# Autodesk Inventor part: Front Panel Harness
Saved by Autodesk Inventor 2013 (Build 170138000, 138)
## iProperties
Created: 2007-02
Part Number: Front Panel Harness
Document SubType Name: Modeling
Designer: floress
Density: 1 g/cm^3
Material: Allgemein
GlobalPropertyList: <PropertyList/>
Key:2|1|1|0|4|0|0|0|19|0|0|0|Level:1: <CableProperty entityType="Connector" version="1.0"><ID editable="" value=""/><UserDefined><Property name="14121" value="0.125 in" unitCategory="14110" custom="
Key:2|1|1|0|8|0|0|0|1|0|0|0|29|0|0|0|Level:2: <CableProperty entityType="Connector" version="1.0"><ID editable="" value=""/><UserDefined><Property name="14121" value="0.125 in" unitCategory="14110" custom="
Author: floress
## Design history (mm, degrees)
workpoint "Work Point1"
workpoint "Work Point2"
sketch "Segment1"
workpoint "Work Point3"
workpoint "Work Point4"
workpoint "Work Point5"
workpoint "Work Point6"
workpoint "Work Point7"
workpoint "Work Point8"
workplane "Work Plane1"
sketch "Sketch1"
  geometry: C1 r 0.986 at (0, 0); 1 further point
  constraints: 1 centre point
feature "SweepSrf1" sketch "Sketch1" dims "d0" = 0
workpoint "Work Point9"
sketch "Segment2"
workpoint "Work Point10"
workplane "Work Plane2"
sketch "Sketch2"
  geometry: C1 r 0.61 at (0, 0); 1 further point
  constraints: 1 centre point
feature "SweepSrf2" sketch "Sketch2" dims "d1" = 0
workpoint "Work Point11"
sketch "Segment3"
workpoint "Work Point12"
workplane "Work Plane3"
sketch "Sketch3"
  geometry: C1 r 0.61 at (0, 0); 1 further point
  constraints: 1 centre point
feature "SweepSrf3" sketch "Sketch3" dims "d2" = 0
workpoint "Work Point13"
sketch "Segment4"
workpoint "Work Point14"
workplane "Work Plane4"
sketch "Sketch4"
  geometry: C1 r 0.61 at (0, 0); 1 further point
  constraints: 1 centre point
feature "SweepSrf4" sketch "Sketch4" dims "d3" = 0
workpoint "Work Point15"
workpoint "Work Point16"
sketch "Wire1"
workpoint "Work Point17"
workpoint "Work Point18"
sketch "Wire2"
workpoint "Work Point19"
workpoint "Work Point20"
sketch "Wire3"
workpoint "Work Point21"
workpoint "Work Point22"
sketch "Wire4"
workpoint "Work Point23"
workpoint "Work Point24"
sketch "Wire5"
workpoint "Work Point25"
workpoint "Work Point26"
sketch "Wire6"
workplane "Work Plane5"
sketch "Sketch5"
  geometry: C1 r 0.305 at (0, 0); 1 further point
  constraints: 1 centre point
feature "SweepSrf5" sketch "Sketch5" dims "d4" = 0
workplane "Work Plane6"
sketch "Sketch6"
  geometry: C1 r 0.305 at (0, 0); 1 further point
  constraints: 1 centre point
feature "SweepSrf6" sketch "Sketch6" dims "d5" = 0
workplane "Work Plane7"
sketch "Sketch7"
  geometry: C1 r 0.305 at (0, 0); 1 further point
  constraints: 1 centre point
feature "SweepSrf7" sketch "Sketch7" dims "d6" = 0
workplane "Work Plane8"
sketch "Sketch8"
  geometry: C1 r 0.305 at (0, 0); 1 further point
  constraints: 1 centre point
feature "SweepSrf8" sketch "Sketch8" dims "d7" = 0
workplane "Work Plane9"
sketch "Sketch9"
  geometry: C1 r 0.305 at (0, 0); 1 further point
  constraints: 1 centre point
feature "SweepSrf9" sketch "Sketch9" dims "d8" = 0
workplane "Work Plane10"
sketch "Sketch10"
  geometry: C1 r 0.305 at (0, 0); 1 further point
  constraints: 1 centre point
feature "SweepSrf10" sketch "Sketch10" dims "d9" = 0
workplane "Work Plane11"
sketch "Sketch11"
  geometry: C1 r 0.305 at (0, 0); 1 further point
  constraints: 1 centre point
feature "SweepSrf11" sketch "Sketch11" dims "d10" = 0
workplane "Work Plane12"
sketch "Sketch12"
  geometry: C1 r 0.305 at (0, 0); 1 further point
  constraints: 1 centre point
feature "SweepSrf12" sketch "Sketch12" dims "d11" = 0
workplane "Work Plane13"
sketch "Sketch13"
  geometry: C1 r 0.305 at (0, 0); 1 further point
  constraints: 1 centre point
feature "SweepSrf13" sketch "Sketch13" dims "d12" = 0
workplane "Work Plane14"
sketch "Sketch14"
  geometry: C1 r 0.305 at (0, 0); 1 further point
  constraints: 1 centre point
feature "SweepSrf14" sketch "Sketch14" dims "d13" = 0
workplane "Work Plane15"
sketch "Sketch15"
  geometry: C1 r 0.305 at (0, 0); 1 further point
  constraints: 1 centre point
feature "SweepSrf15" sketch "Sketch15" dims "d14" = 0
workplane "Work Plane16"
sketch "Sketch16"
  geometry: C1 r 0.305 at (0, 0); 1 further point
  constraints: 1 centre point
feature "SweepSrf16" sketch "Sketch16" dims "d15" = 0
body "Srf1"
body "Srf2"
body "Srf3"
body "Srf4"
body "Srf5"
body "Srf6"
body "Srf7"
body "Srf8"
body "Srf9"
body "Srf10"
body "Srf11"
body "Srf12"
body "Srf13"
body "Srf14"
body "Srf15"
body "Srf16"
